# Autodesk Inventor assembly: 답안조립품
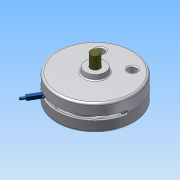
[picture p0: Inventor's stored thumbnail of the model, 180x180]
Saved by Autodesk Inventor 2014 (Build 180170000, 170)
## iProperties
Created: 2015-06
Part Number: 답안조립품
Document SubType Name: Assembly
Designer: Administrator
Author: Administrator
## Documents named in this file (10)
- C:\Documents and Settings\Administrator\바탕 화면\450631V1003\답안조립품.iam
- C:\Documents and Settings\Administrator\바탕 화면\450631V1003\본체.ipt
- C:\Documents and Settings\Administrator\바탕 화면\450631V1003\덮개.ipt
- C:\Documents and Settings\Administrator\바탕 화면\450631V1003\베어링62_22.ipt
- C:\Documents and Settings\Administrator\바탕 화면\450631V1003\축.ipt
- C:\Documents and Settings\Administrator\바탕 화면\450631V1003\멈춤링.ipt
- C:\Documents and Settings\Administrator\바탕 화면\450631V1003\M10x35.ipt
- C:\Documents and Settings\Administrator\바탕 화면\450631V1003\슬라이더.ipt
- C:\Documents and Settings\Administrator\바탕 화면\450631V1003\슬라이더2.ipt
- C:\Documents and Settings\Administrator\바탕 화면\450631V1003\평행핀.ipt
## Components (7 placed, 4 different names)
1. KS B 1336 22 x 1.2:1
2. KS B 1336 22 x 1.2:2
3. KS B 1003 - 미터 M 10 x 35:1
4. KS B 1003 - 미터 M 10 x 35:2
5. KS B 2023 62/22 - 22 x 50 x 14:2
6. KS B 2023 62/22 - 22 x 50 x 14:3
7. KS B 1320 B B 5 x  20:1
